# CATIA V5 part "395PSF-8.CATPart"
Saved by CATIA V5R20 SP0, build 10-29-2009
Part number: 395PSF-8
Source: Unknown
Property "ARTICLENO": "395PSF-8"
Property "BOMINFO": "395PSF-8"
Property "CODE": "395PSF-8"
Property "D": "63.000"
Property "D1": "78.000"
Property "H": "7.500"
Property "L": "272.500"
Property "L1": "12.000"
Property "L2": "215.000"
Property "L3": "20.000"
Property "L4": "12.000"
Property "LINA": "395PSF-8"
Property "MAXLOAD": "13000 Kg"
Property "MDW": "26000 Kg"
Property "NB": "395PSF-8"
Property "NBSYN": "$CODE."
Property "NN": "395PSF"
Property "NT": "FIAT Lifting Pins"
Property "SUPPLIER": "CF"
Bounding box of the stored display mesh (mm): x 0 to 272.5, y -39 to 39, z -39 to 39
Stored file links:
  C:\Users\Utente\Desktop\3D files 395PSF\395PSF-8.CATPart
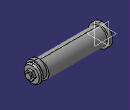
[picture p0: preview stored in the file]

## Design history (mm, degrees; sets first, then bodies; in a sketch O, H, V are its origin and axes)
Body1 "Geometry.1" (main body)
  Solid1 "395PSF-8.catpart": solid without history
